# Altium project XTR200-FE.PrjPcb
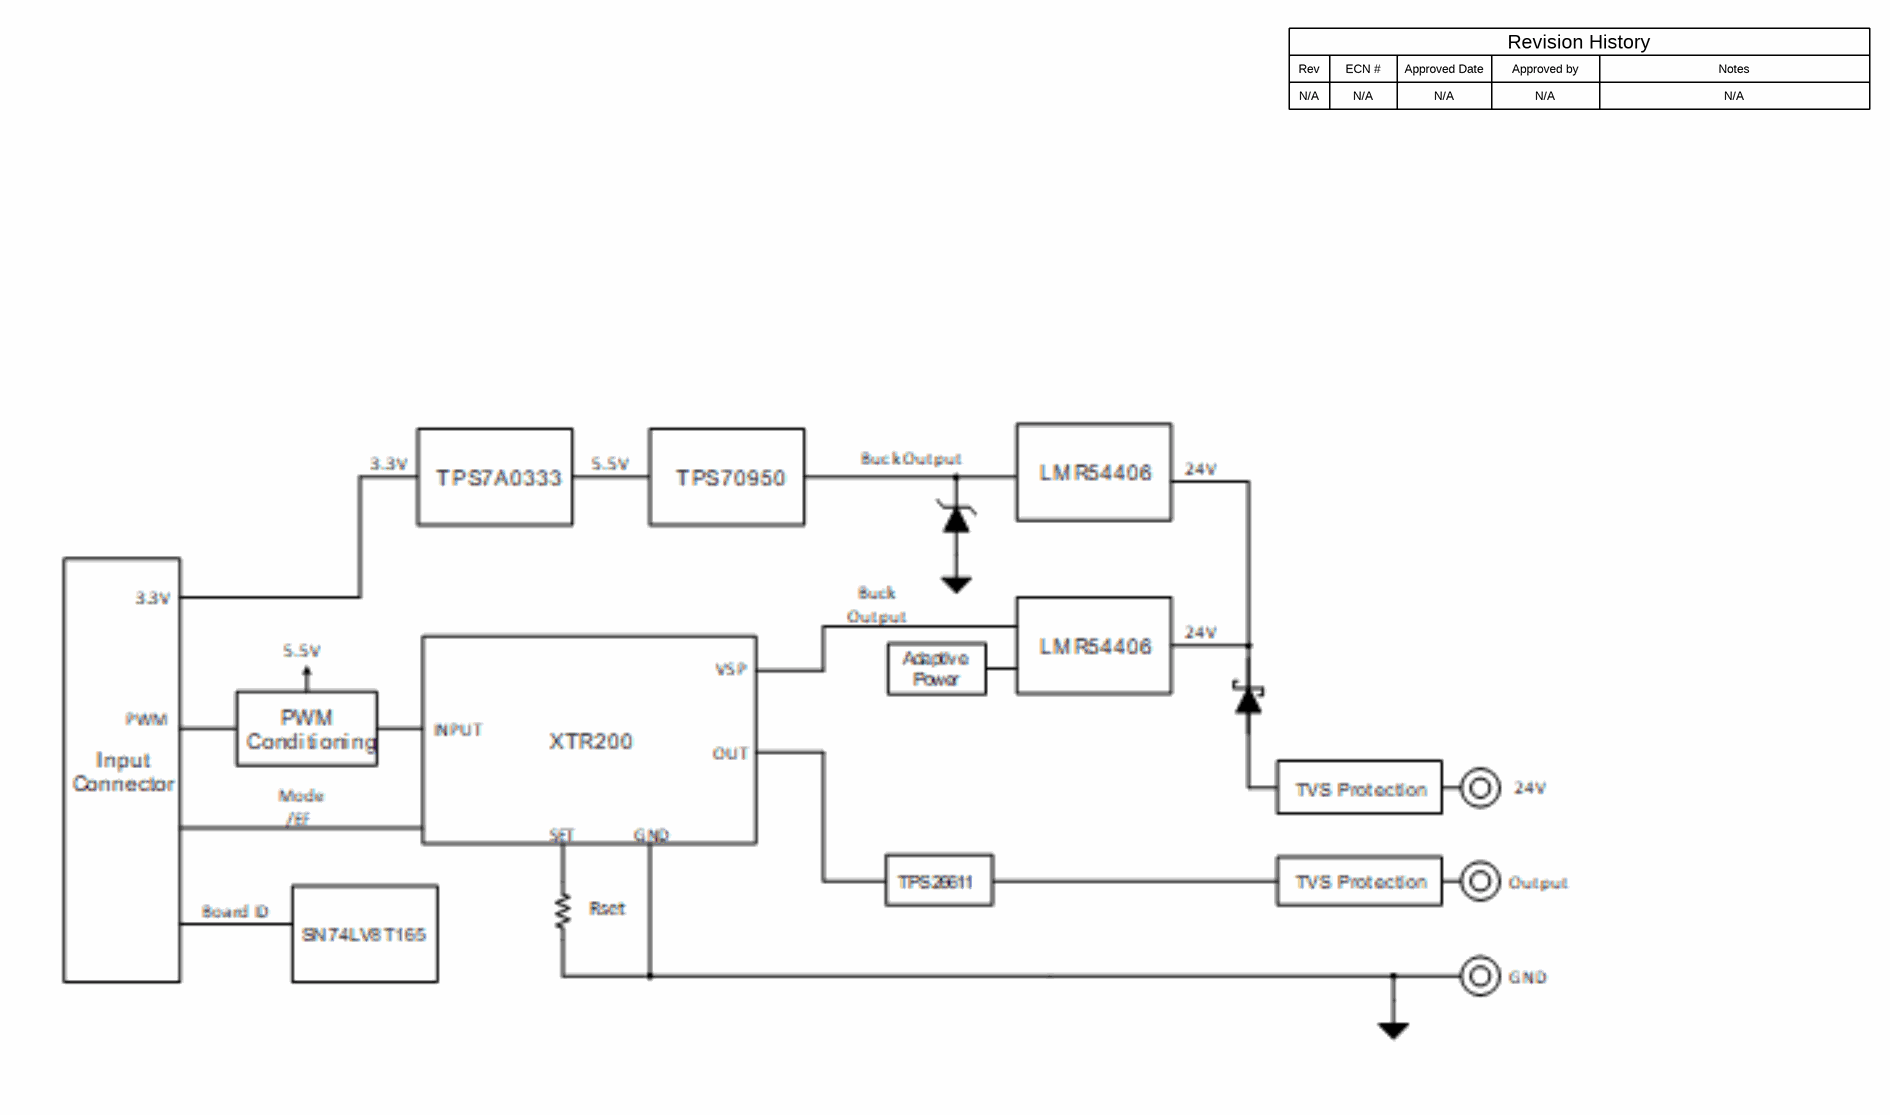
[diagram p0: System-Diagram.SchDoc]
TID: TIDA-011026; TechSupport: http://www.ti.com/support; SCH_Rev: A1; PRJ_Title: FT-EVP-XTR200; PRJ_Number: XTR200_FT; PRJ_Engineer: S. Rojas Avila; PRJ_Customer: Public Release; PCB_Rev: A1; PCB_Layout: S. Rojas Avila; CopyrightYear: 2024
3 sheets, 94 parts. Net scope: global (net labels, ports and power ports of the same name join across sheets).
Board file: XTR200FTA.PcbDoc
Sheets:
  System-Diagram.SchDoc
  Schematic.SchDoc
  Hardware.SchDoc

## Sheet System-Diagram.SchDoc
size 431 x 279 mm; Date: Not shown in title block; ApprovedBy: Not shown in title block; CheckedBy: Not shown in title block; Author: Not shown in title block; CompanyName: Not shown in title block; Engineer: Not shown in title block; Organization: Not shown in title block; Address1: Not shown in title block; Address2: Not shown in title block; Address3: Not shown in title block; Address4: Not shown in title block; DocumentNumber: 1; Revision: Use project parameter SCH_Rev; SheetNumber: 1; SheetTotal: 3; PageSetup: Record=PageOptions¦CenterHorizontal=True¦CenterVertical=True¦PrintScale=1.00¦XCorrection=1.00¦YCorrection=1.00¦PrintKind=0¦BorderSize=5000000¦LeftOffset=0¦BottomOffset=0¦Orientation=2¦PaperLength=1000¦PaperWidth=1000¦Scale=100¦PaperSource=15¦PrintQuality=600¦MediaType=1¦DitherType=10¦PaperKind=Letter¦PrintScaleMode=1

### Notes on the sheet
- Rev
- N/A
- ECN #
- Approved Date
- Approved by
- Revision History
- Notes

## Sheet Schematic.SchDoc
size 431 x 279 mm; Date: Not shown in title block; ApprovedBy: Not shown in title block; CheckedBy: Not shown in title block; Author: Not shown in title block; CompanyName: Not shown in title block; Engineer: Not shown in title block; Organization: Not shown in title block; Address1: Not shown in title block; Address2: Not shown in title block; Address3: Not shown in title block; Address4: Not shown in title block; DocumentNumber: 2; Revision: Use project parameter SCH_Rev; SheetNumber: 2; SheetTotal: 3; PageSetup: Record=PageOptions¦CenterHorizontal=True¦CenterVertical=True¦PrintScale=1.00¦XCorrection=1.00¦YCorrection=1.00¦PrintKind=0¦BorderSize=5000000¦LeftOffset=0¦BottomOffset=0¦Orientation=2¦PaperLength=1000¦PaperWidth=1000¦Scale=100¦PaperSource=15¦PrintQuality=600¦MediaType=1¦DitherType=10¦PaperKind=Letter¦PrintScaleMode=1
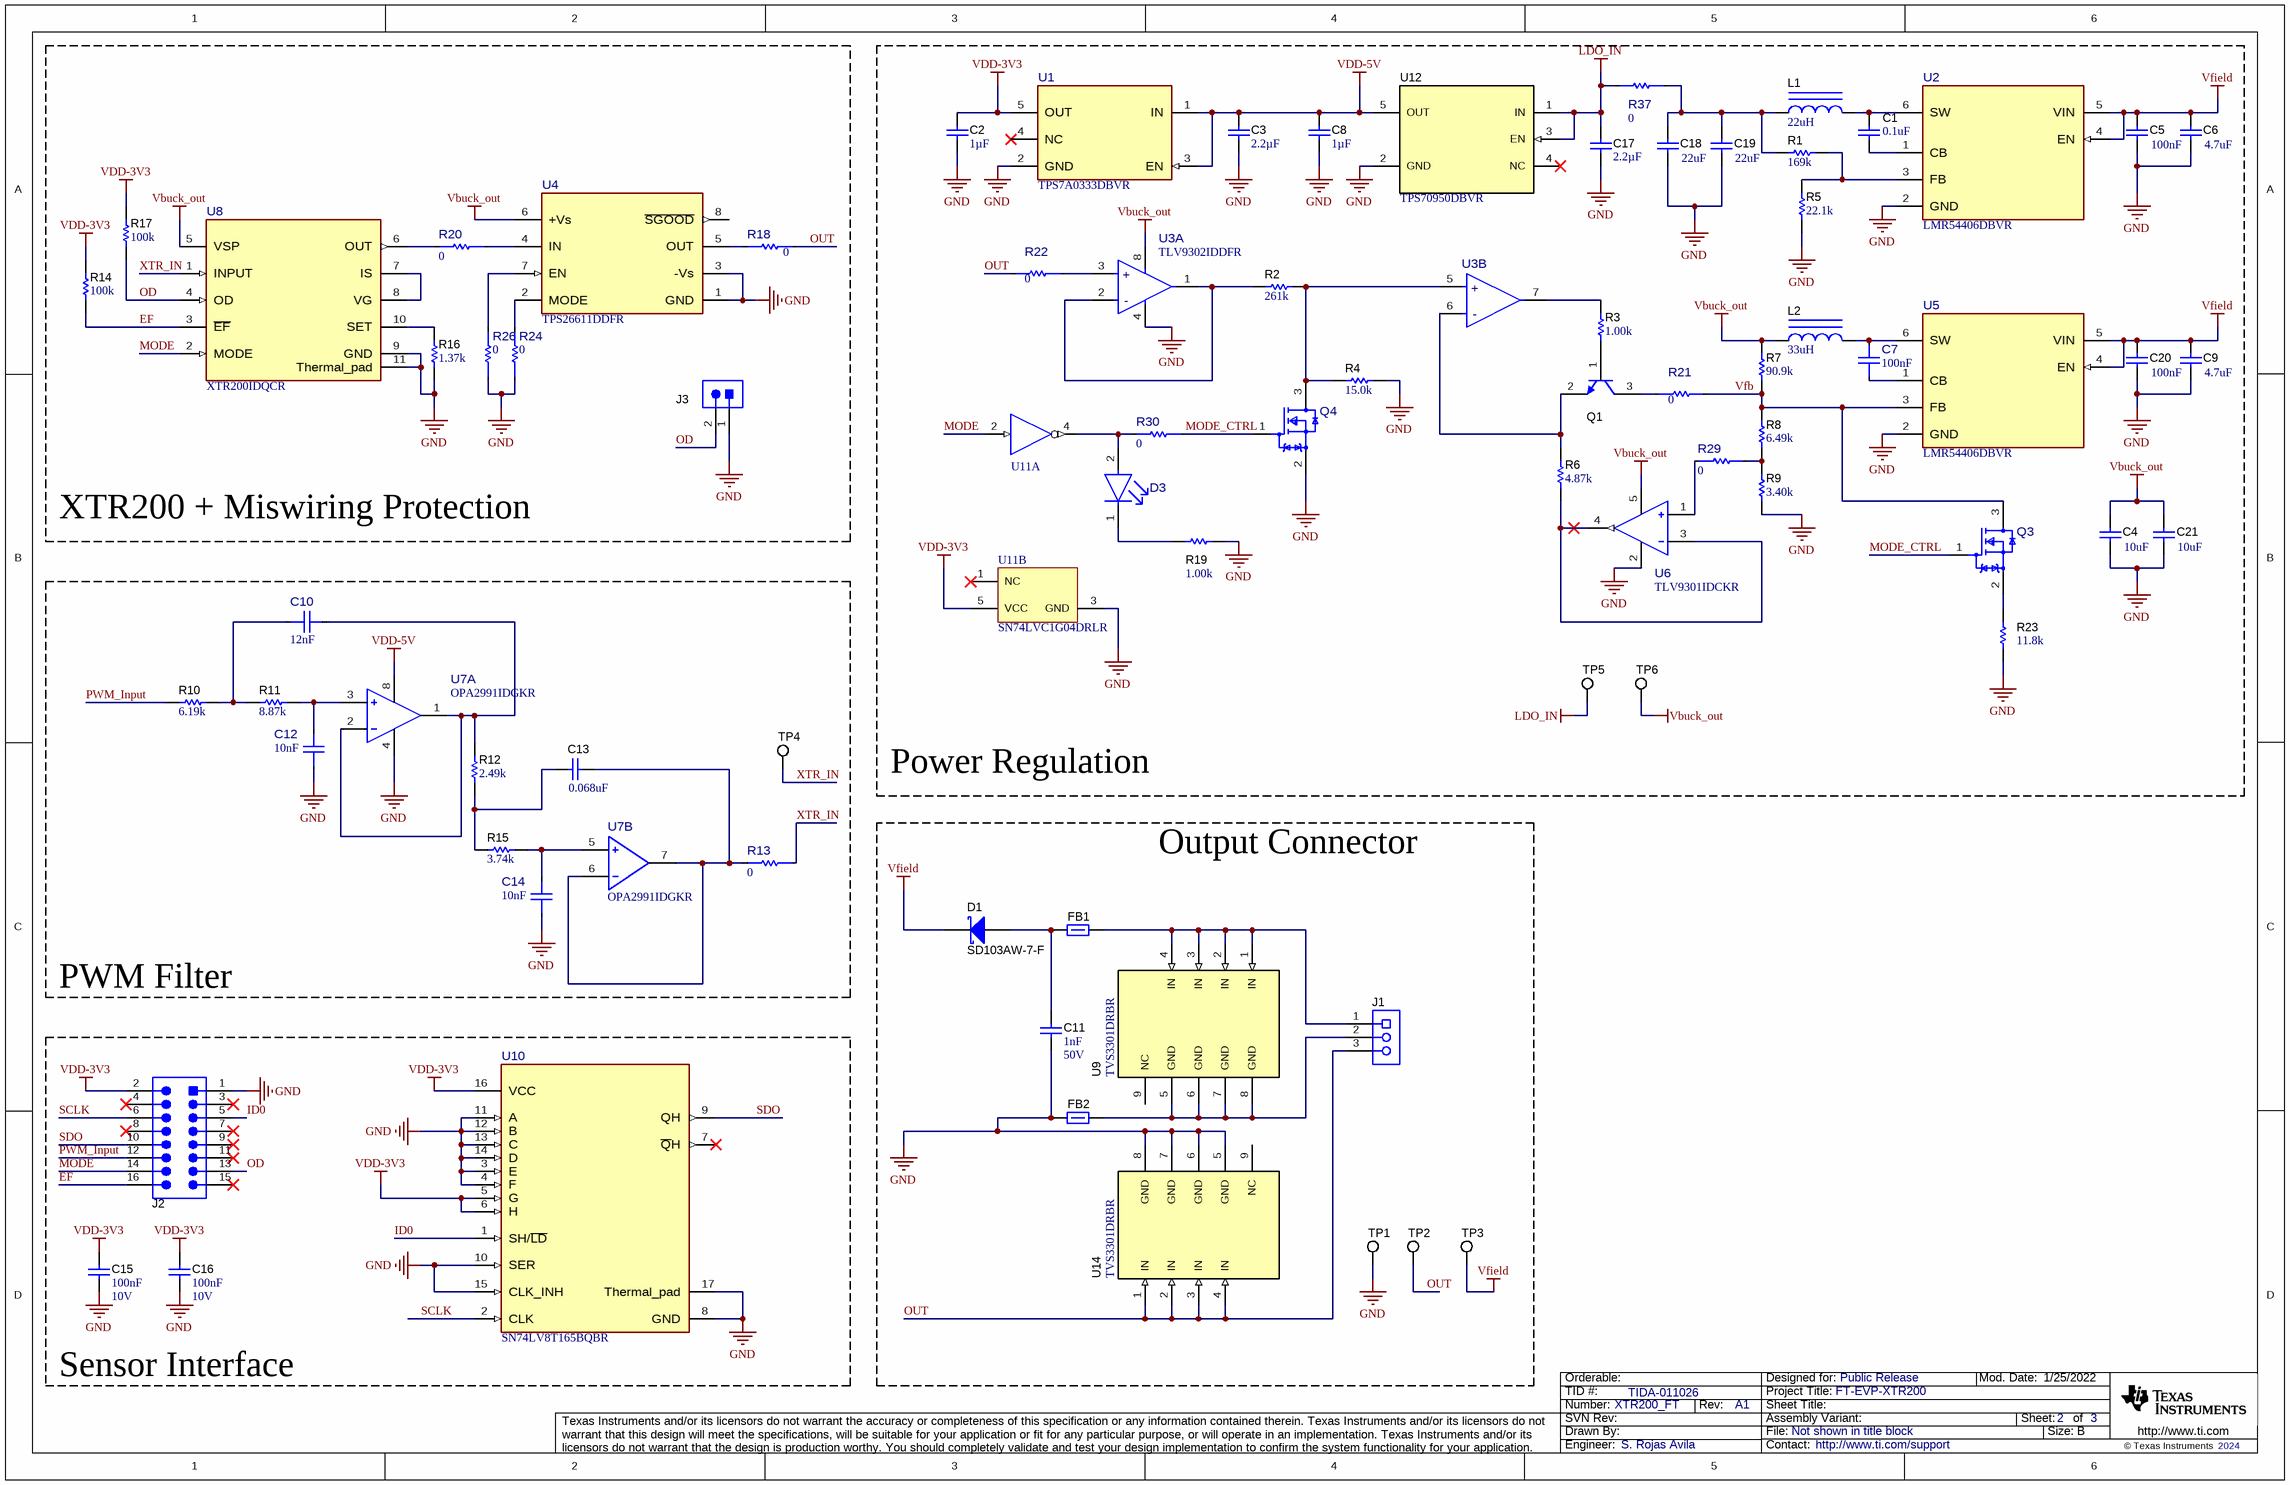
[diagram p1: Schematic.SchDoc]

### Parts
C1  ValueDisplayed: 0.1uF  [0402]  (hidden comment: GRM155R71C104KA88D)
C2  Cap_F: 1µF  [0603]  (hidden comment: 885012206052)
C3  Cap_F: 2.2µF  [0805_HV]  (hidden comment: GRM21BR71C225KA12L)
C4  ValueDisplayed: 10uF  [1206_180]  (hidden comment: C3216X6S1V106K160AC)
C5  Cap_F: 100nF  [0603]  (hidden comment: GRM188R72A104KA35D)
C6  ValueDisplayed: 4.7uF  [1206_180]  (hidden comment: GRM31CR71H475KA12L)
C7  Cap_F: 100nF  [FP-KGF15AR71H104KT_0603-MFG]  (hidden comment: KGF15AR71H104KT)
C8  Cap_F: 1µF  [0603]  (hidden comment: 885012206052)
C9  ValueDisplayed: 4.7uF  [0805_HV]  (hidden comment: GRM21BR61H475KE51L)
C10  ValueDisplayed: 12nF  [FP-CC0402KRX7R7BB123_0402-MFG]  (hidden comment: CC0402KRX7R7BB123)
C11  Cap_F: 1nF  VDC_V: 50V  [0805_HV]  (hidden comment: CC0805KRX7R9BB102)
C12  Cap_F: 10nF  [FP-GRM155R71H103JA88D_0402-MFG]  (hidden comment: GRM155R71H103JA88D)
C13  ValueDisplayed: 0.068uF  [0402]  (hidden comment: GRM155R71C683KA88D)
C14  Cap_F: 10nF  [FP-GRM155R71H103JA88D_0402-MFG]  (hidden comment: GRM155R71H103JA88D)
C15  Cap_F: 100nF  VDC_V: 10V  [0603]  (hidden comment: 885012206020)
C16  Cap_F: 100nF  VDC_V: 10V  [0603]  (hidden comment: 885012206020)
C17  Cap_F: 2.2µF  [0805_HV]  (hidden comment: GRM21BR71C225KA12L)
C18  ValueDisplayed: 22uF  [0805_HV]  (hidden comment: GRM21BR61A226ME44L)
C19  ValueDisplayed: 22uF  [0805_HV]  (hidden comment: GRM21BR61A226ME44L)
C20  Cap_F: 100nF  [0603]  (hidden comment: GRM188R72A104KA35D)
C21  ValueDisplayed: 10uF  [1206_180]  (hidden comment: C3216X6S1V106K160AC)
D1  SD103AW-7-F  [SOD-123]
D3  LTST-C190KFKT  [FP-LTST-C190KFKT_0603-MFG]  (value not drawn)
FB1  742792041  [0805_HV]  (value not drawn)
FB2  742792041  [0805_HV]  (value not drawn)
J1  691412320003  [Wurth_691412320003]  (value not drawn)
J2  61301621021  [Wurth_61301621021]  (value not drawn)
J3  61300211121  [WURTH_61300211121]  (value not drawn)
L1  ValueDisplayed: 22uH  [SRN8040]  (hidden comment: SRN8040-220M)
L2  ValueDisplayed: 33uH  [SRN8040]  (hidden comment: SRN8040-330M)
Q1  MMBT3904LP  [DIODES_X1-DFN1006-3]  (value not drawn)
Q3  NTR4003NT3G  [FP-NTR4003NT3G_SOT23-3-MFG]  (value not drawn)
Q4  NTR4003NT3G  [FP-NTR4003NT3G_SOT23-3-MFG]  (value not drawn)
R1  ValueDisplayed: 169k  [0603]  (hidden comment: CRCW0603169KFKEA)
R2  ValueDisplayed: 261k  [0603]  (hidden comment: CRCW0603261KFKEA)
R3  ValueDisplayed: 1.00k  [0402]  (hidden comment: ERA-2AEB102X)
R4  ValueDisplayed: 15.0k  [0402]  (hidden comment: RC0402FR-0715KL)
R5  ValueDisplayed: 22.1k  [0402]  (hidden comment: CRCW040222K1FKED)
R6  ValueDisplayed: 4.87k  [0603]  (hidden comment: RC0603FR-074K87L)
R7  ValueDisplayed: 90.9k  [0603]  (hidden comment: RC0603FR-0790K9L)
R8  ValueDisplayed: 6.49k  [0603]  (hidden comment: RT0603BRD076K49L)
R9  ValueDisplayed: 3.40k  [0603]  (hidden comment: RT0603BRD073K4L)
R10  ValueDisplayed: 6.19k  [0603]  (hidden comment: RC0603FR-076K19L)
R11  ValueDisplayed: 8.87k  [0603]  (hidden comment: RT0603DRE078K87L)
R12  ValueDisplayed: 2.49k  [0603]  (hidden comment: RT0603DRE072K49L)
R13  value 0  [FP-WSL060300000ZEA9_0603-MFG]  (hidden comment: WSL060300000ZEA9)
R14  ValueDisplayed: 100k  [0603]  (hidden comment: RG1608P-104-B-T5)
R15  ValueDisplayed: 3.74k  [0603]  (hidden comment: RT0603DRE073K74L)
R16  ValueDisplayed: 1.37k  [0603]  (hidden comment: RT0603BRD071K37L)
R17  ValueDisplayed: 100k  [0603]  (hidden comment: RG1608P-104-B-T5)
R18  value 0  [FP-WSL060300000ZEA9_0603-MFG]  (hidden comment: WSL060300000ZEA9)
R19  ValueDisplayed: 1.00k  [0603]  (hidden comment: RT0603DRE071KL)
R20  value 0  [FP-WSL060300000ZEA9_0603-MFG]  (hidden comment: WSL060300000ZEA9)
R21  value 0  [FP-WSL060300000ZEA9_0603-MFG]  (hidden comment: WSL060300000ZEA9)
R22  value 0  [FP-WSL060300000ZEA9_0603-MFG]  (hidden comment: WSL060300000ZEA9)
R23  ValueDisplayed: 11.8k  [0603]  (hidden comment: RT0603BRD0711K8L)
R24  value 0  [FP-WSL060300000ZEA9_0603-MFG]  (hidden comment: WSL060300000ZEA9)
R26  value 0  [FP-WSL060300000ZEA9_0603-MFG]  (hidden comment: WSL060300000ZEA9)
R29  value 0  [FP-WSL060300000ZEA9_0603-MFG]  (hidden comment: WSL060300000ZEA9)
R30  value 0  [FP-WSL060300000ZEA9_0603-MFG]  (hidden comment: WSL060300000ZEA9)
R37  value 0  [FP-WSL060300000ZEA9_0603-MFG]  (hidden comment: WSL060300000ZEA9)
TP1  GND  [Keystone5002]  (value not drawn)
TP2  GND  [Keystone5002]  (value not drawn)
TP3  GND  [Keystone5002]  (value not drawn)
TP4  GND  [Keystone5002]  (value not drawn)
TP5  GND  [Keystone5002]  (value not drawn)
TP6  GND  [Keystone5002]  (value not drawn)
U1  TPS7A0333DBVR  [DBV0005A-MFG]
U2  LMR54406DBVR  [DBV0006A-MFG]
U3  TLV9302IDDFR  [DDF0008A-MFG]  (parts A,B of 2)
U4  TPS26611DDFR  [DDF0008A-MFG]
U5  LMR54406DBVR  [DBV0006A-MFG]
U6  TLV9301IDCKR  [DCK0005A-MFG]
U7  OPA2991IDGKR  [DGK0008A-MFG]  (parts A,B of 2)
U8  XTR200IDQCR  [DQC0010A-MFG]
U9  TVS3301DRBR  [DRB0008A]
U10  SN74LV8T165BQBR  [BQB0016A-MFG]
U11  SN74LVC1G04DRLR  [DRL0005A]  (value not drawn)  (parts A,B of 2)
U12  TPS70950DBVR  [DBV0005A_N]
U14  TVS3301DRBR  [DRB0008A]

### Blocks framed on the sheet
XTR200 + Miswiring Protection: J3 R14 R16-R18 R20 R24 R26 U4 U8
Power Regulation: C1-C9 C17-C21 D3 L1 L2 Q1 Q3 Q4 R1-R9 R19 R21-R23 R29 R30 R37 TP5 TP6 U1-U3 U5 U6 U11 U12
PWM Filter: C10 C12-C14 R10-R13 R15 TP4 U7
Output Connector: C11 D1 FB1 FB2 J1 TP1-TP3 U9 U14
Sensor Interface: C15 C16 J2 U10

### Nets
GND: C2.1 C3.1 C4.1 C5.2 C6.2 C8.1 C9.2 C11.2 C12.1 C14.1 C15.2 C16.2 C17.1 C18.2 C19.2 C20.2 C21.1 FB2.1 J2.1 J3.1 Q4.2(SOURCE) R4.1 R5.1 R9.1 R16.1 R19.2 R23.1 R24.1 R26.1 TP1.1 U1.2(GND) U2.2(GND) U3.4(V-) U4.1(GND) U4.3(-Vs) U5.2(GND) U6.2(V-) U7.4(V-) U8.9(GND) U8.11(Thermal_pad) U10.3(E) U10.4(F) U10.8(GND) U10.10(SER) U10.11(A) U10.12(B) U10.13(C) U10.14(D) U10.15(CLK_INH) U10.17(Thermal_pad) U11.3(GND) U12.2(GND) U14.5(GND) U14.6(GND) U14.7(GND) U14.8(GND)
LDO_IN: C17.2 R37.2 TP5.1 U12.1(IN) U12.3(EN)
Vbuck_out: C4.2 C21.2 L2.1 R7.2 TP6.1 U3.8(V+) U4.6(+Vs) U6.5(V+) U8.5(VSP)
VDD-3V3: C2.2 C15.1 C16.1 J2.2 R14.2 R17.2 U1.5(OUT) U10.5(G) U10.6(H) U10.16(VCC) U11.5(VCC)
VDD-5V: C3.2 C8.2 U1.1(IN) U1.3(EN) U7.8(v+) U12.5(OUT)
Vfield: C5.1 C6.1 C9.1 C20.1 D1.1(K) TP3.1 U2.4(EN) U2.5(VIN) U5.4(EN) U5.5(VIN)
EF: J2.16 R14.1 U8.3(~{EF})
ID0: J2.5 U10.1(SH/~{LD})
MODE: J2.14 U8.2(MODE) U11.2(A)
MODE_CTRL: Q3.1(GATE) Q4.1(GATE) R30.1
OD: J2.13 J3.2 R17.1 U8.4(OD)
OUT: J1.3 R18.1 R22.2 TP2.1 U14.1(IN) U14.2(IN) U14.3(IN) U14.4(IN)
PWM_Input: J2.12 R10.1
SCLK: J2.6 U10.2(CLK)
SDO: J2.10 U10.9(QH)
Vfb: Q3.3(DRAIN) R7.1 R8.2 R21.2 U5.3(FB)
XTR_IN: R13.1 TP4.1 U8.1(INPUT)
NetC1_1: C1.1 L1.2 U2.6(SW)
NetC1_2: C1.2 U2.1(CB)
NetC7_1: C7.1 U5.1(CB)
NetC7_2: C7.2 L2.2 U5.6(SW)
NetC10_1: C10.1 R10.2 R11.1
NetC10_2: C10.2 R12.2 U7.1(OUT1) U7.2(IN1-)
NetC11_1: C11.1 D1.2(A) FB1.1
NetC12_2: C12.2 R11.2 U7.3(IN1+)
NetC13_1: C13.1 R13.2 U7.6(IN2-) U7.7(OUT2)
NetC13_2: C13.2 R12.1 R15.1
NetC14_2: C14.2 R15.2 U7.5(IN2+)
NetC18_1: C18.1 C19.1 L1.1 R1.2 R37.1
NetD3_1: D3.1(CATHODE) R19.1
NetD3_2: D3.2(ANODE) R30.2 U11.4(Y)
NetFB1_2: FB1.2 J1.1 U9.1(IN) U9.2(IN) U9.3(IN) U9.4(IN)
NetFB2_2: FB2.2 J1.2 U9.5(GND) U9.6(GND) U9.7(GND) U9.8(GND)
NetQ1_1: Q1.1(B) R3.2
NetQ1_2: Q1.2(E) R6.2 U3.6(IN2-)
NetQ1_3: Q1.3(C) R21.1
NetQ3_2: Q3.2(SOURCE) R23.2
NetQ4_3: Q4.3(DRAIN) R2.2 R4.2 U3.5(IN2+)
NetR1_1: R1.1 R5.2 U2.3(FB)
NetR2_1: R2.1 U3.1(OUT1) U3.2(IN1-)
NetR3_1: R3.1 U3.7(OUT2)
NetR6_1: R6.1 U6.3(IN-) U6.4(OUT)
NetR8_1: R8.1 R9.2 R29.2
NetR16_2: R16.2 U8.10(SET)
NetR18_2: R18.2 U4.5(OUT)
NetR20_1: R20.1 U4.4(IN)
NetR20_2: R20.2 U8.6(OUT)
NetR22_1: R22.1 U3.3(IN1+)
NetR24_2: R24.2 U4.2(MODE)
NetR26_2: R26.2 U4.7(EN)
NetR29_1: R29.1 U6.1(IN+)
NetU8_7: U8.7(IS) U8.8(VG)

Not connected (* = marked no-connect by the designer): J2 3* 4* 7* 8* 9* 11* 15*; U1 4(NC)*; U4 8(~{SGOOD}); U9 9(NC); U10 7(~{Q}H)*; U11 1(NC)*; U12 4(NC)*; U14 9(NC)

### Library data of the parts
C1 = CMP-0006641-2: CAP, CERM, 0.1 uF, 16 V, +/- 10%, X7R, 0402; Manufacturer: MuRata; TaMin_C: -55°C; Polarized: N; SizeAreaWB_mm2: 3; Value1: Unknown; U/M: EA; Value: 0.1uF; TaMax_C: 125°C; SizeZ_mm: 0.6; SizeX_mm: 1; SizeY_mm: 0.5; Value2: 16V; Cap_F: 100nF; AEC Category: Q200
C2 C8 = CMP-0006831-4: CAP, CERM, 1 uF, 16 V, +/- 10%, X7R, 0603; Manufacturer: Wurth Elektronik; TaMin_C: -55°C; Polarized: N; SizeAreaWB_mm2: 4.68; Value1: Unknown; U/M: EA; Value: 1uF; TaMax_C: 125°C; SizeZ_mm: 1; SizeX_mm: 1.6; SizeY_mm: 0.8; Value2: 16V; SizeArea_mm2: 1.28; AEC Category: Q200
C3 C17 = CMP-0008329-2: CAP, CERM, 2.2 uF, 16 V, +/- 10%, X7R, 0805; Manufacturer: MuRata; TaMin_C: -55°C; ESR_ohm: 4m; Polarized: N; SizeAreaWB_mm2: 6.75; Value1: 0.004 ohm; U/M: EA; Value: 2.2uF; TaMax_C: 125°C; SizeZ_mm: 1.45; SizeX_mm: 2; SizeY_mm: 1.25; Cap_Case: 0805; Value2: 16V; SizeArea_mm2: 2.5; AEC Category: Q200
C4 C21 = CMP-0008684-3: CAP, CERM, 10 uF, 35 V, +/- 10%, X6S, 1206; Manufacturer: TDK; TaMin_C: -55°C; ESR_ohm: 2.229m; Polarized: N; SizeAreaWB_mm2: 10.92; Value1: 0.002229 ohm; U/M: EA; Value: 10uF; TaMax_C: 105°C; SizeZ_mm: 1.8; SizeX_mm: 3.2; SizeY_mm: 1.6; Value2: 35V; SizeArea_mm2: 5.12; Cap_F: 10µF; IRMS_A: 4.85932A; AEC Category: Q200
C5 C20 = CMP-0007469-4: CAP, CERM, 0.1 uF, 100 V, +/- 10%, X7R, 0603; Manufacturer: MuRata; TaMin_C: -55°C; Polarized: N; SizeAreaWB_mm2: 4.68; Value1: Unknown; U/M: EA; Value: 0.1uF; TaMax_C: 125°C; SizeZ_mm: 1; SizeX_mm: 1.6; SizeY_mm: 0.8; Value2: 100V; SizeArea_mm2: 1.28; AEC Category: Q200
C6 = CMP-0008969-2: CAP, CERM, 4.7 uF, 50 V, +/- 10%, X7R, 1206; Manufacturer: MuRata; TaMin_C: -55°C; Polarized: N; SizeAreaWB_mm2: 10.92; Value1: Unknown; U/M: EA; Value: 4.7uF; TaMax_C: 125°C; SizeZ_mm: 1.8; SizeX_mm: 3.2; SizeY_mm: 1.6; Cap_Case: 2220; Value2: 50V; SizeArea_mm2: 5.12; Cap_F: 4.7µF; AEC Category: Q200
C7 = CMP-0121004-1: 0.1 µF ±10% 50V Ceramic Capacitor X7R 0603 (1608 Metric); Manufacturer: KYOCERA AVX; AEC Qualified: No; SizeZ_mm: 0.9mm; TempCo: 15%; Value: 100nF
C9 = CMP-0008309-2: CAP, CERM, 4.7 uF, 50 V, +/- 10%, X5R, 0805; Manufacturer: MuRata; TaMin_C: -55°C; Polarized: N; SizeAreaWB_mm2: 6.75; Value1: Unknown; U/M: EA; Value: 4.7uF; TaMax_C: 85°C; SizeZ_mm: 1.45; SizeX_mm: 2; SizeY_mm: 1.25; Cap_Case: 0805; Value2: 50V; SizeArea_mm2: 2.5; Cap_F: 4.7µF; AEC Category: Q200
C10 = CMP-0109222-1: 0.012 µF ±10% 16V Ceramic Capacitor X7R 0402 (1005 Metric); Manufacturer: Yageo; AEC Qualified: No; SizeZ_mm: 0.55mm; TempCo: 15%; Value: 12nF
C11 = CMP-0007936-2: CAP, CERM, 1000 pF, 50 V, +/- 10%, X7R, 0805; Manufacturer: Yageo America; TaMin_C: -55°C; Polarized: N; SizeAreaWB_mm2: 6.75; Value1: Unknown; U/M: EA; Value: 1000pF; TaMax_C: 125°C; SizeZ_mm: 1.45; SizeX_mm: 2; SizeY_mm: 1.25; Cap_Case: 0805; SizeArea_mm2: 2.5; AEC Category: Q200
C12 C14 = CMP-0096544-1: Chip Multilayer Ceramic Capacitors for General Purpose, 0402, 10000pF, X7R, 15%, 5%, 50V; Manufacturer: Murata; Value: 10nF; SizeZ_mm: 0.55mm; AEC Qualified: No
C13 = CMP-0006655-2: CAP, CERM, 0.068 uF, 16 V, +/- 10%, X7R, 0402; Manufacturer: MuRata; TaMin_C: -55°C; Polarized: N; SizeAreaWB_mm2: 3; Value1: Unknown; U/M: EA; TaMax_C: 125°C; SizeZ_mm: 0.6; SizeX_mm: 1; SizeY_mm: 0.5; Value2: 16V; Cap_F: 68nF; AEC Category: Q200
C15 C16 = CMP-0064931-4: CAP, CERM, 0.1 uF, 10 V,+/- 10%, X7R, 0603; Manufacturer: Wurth Elektronik; TaMin_C: -55°C; Polarized: N; SizeAreaWB_mm2: 4.68; Value1: Unknown; U/M: EA; Value: 0.1uF; TaMax_C: 125°C; SizeZ_mm: 1; SizeX_mm: 1.6; SizeY_mm: 0.8; SizeArea_mm2: 1.28; AEC Category: Q200
C18 C19 = CMP-0008286-2: CAP, CERM, 22 uF, 10 V, +/- 20%, X5R, 0805; Manufacturer: MuRata; TaMin_C: -55°C; Polarized: N; SizeAreaWB_mm2: 6.75; Value1: Unknown; U/M: EA; Value: 22uF; TaMax_C: 85°C; SizeZ_mm: 1.45; SizeX_mm: 2; SizeY_mm: 1.25; Cap_Case: 0805; Value2: 10V; SizeArea_mm2: 2.5; Cap_F: 22µF; AEC Category: Q200
D1 = CMP-0028543-2: Diode, Schottky, 40 V, 0.35 A, SOD-123; Manufacturer: Diodes Inc.; AEC Category: Q101; Io_A: 350mA; SizeZ_mm: 1.35; Vf_V: 550mV; Green_REACh: Passed; SizeAreaWB_mm2: 13.095; SizeY_mm: 1.7; SizeX_mm: 3.85; Value2: 0.55V; Green_Lifecycle: Active; Vr_V: 40V; Value1: 0.35A; SizeArea_mm2: 6.545; Value: 40V
D3 = CMP-0097262-1: Orange 605nm LED Indication - Discrete 2V 0603 (1608 Metric); Manufacturer: Lite-On; Vr_V: 5V; SizeZ_mm: 0.9mm; AEC Qualified: No; Led Orientation: Top View; Forward Current: 20mA; Power_TotalModule: 75mW; Luminous Intensity: 90mcd; LambdaP: 611nm; Angle: 130°
FB1 FB2 = CMP-0003085-1: Ferrite Bead, 600 ohm @ 100 MHz, 0.2 A, 0805; Manufacturer: Wurth Elektronik; Ztyp@1GHz_Ohm: 200.287; ZTyp@100MHz_Ohm: 600; SizeAreaWB_mm2: 6.75; DCR_ohm: 0.4; Value1: 0.4 ohm; Value: 600 ohm; Imax_A: 200mA; SizeZ_mm: 1.45; SizeX_mm: 2; SizeY_mm: 1.25; Value2: 0.2A; SizeArea_mm2: 2.5
J1 = CMP-0083843-1: Terminal Block, 3 Position, 3.81mm, Tin, R/A, TH; Manufacturer: Wurth Elektronik; Pitch_mm: 3.81; Voltage_V: 300V; Cert_UL: Y; Gender: Female; Current_A: 4A; Row_Count: 1
J2 = CMP-0081505-1: Header, 2.54mm, 8x2, Gold, R/A, TH; Manufacturer: Wurth Elektronik; Pitch_mm: 2.54; Gender: Male; Cert_UL: Y; Current_A: 3A; Voltage_V: 250V; Shrouded: N; Row_Count: 2
J3 = CMP-0054794-2: Header, 2.54 mm, 2x1, Gold, TH; Manufacturer: Wurth Elektronik; Shrouded: N; Gender: Male; Green_REACh: Passed; Pitch_mm: 2.54; Green_Lifecycle: Active; Row_Count: 1; Cert_UL: Y
L1 = CMP-0057669-2: Inductor, Drum Core, Ferrite, 22 uH, 2.2 A, 0.1 ohm, SMD; Manufacturer: Bourns; Isat: 2.2A @ 30% inductance drop; Irms: 2.2A @ 40C rise; Green_Lifecycle: Active; SizeAreaWB_mm2: 100; DCR_ohm: 1d; Green_REACh: Passed; Value1: 0.1 ohm; Value: 22uH; Imax_A: 2.2A; SizeZ_mm: 4; SizeX_mm: 8; SizeArea_mm2: 64; Ind_H: 22µH; AEC Category: Q200
L2 = CMP-0057670-2: Inductor, Drum Core, Ferrite, 33 uH, 1.7 A, 0.145 ohm, SMD; Manufacturer: Bourns; Isat: 1.9A @ 30% inductance drop; Irms: 1.7A @ 40C rise; Green_Lifecycle: Active; SizeAreaWB_mm2: 100; DCR_ohm: 1.45d; Green_REACh: Passed; Value: 33uH; Imax_A: 1.7A; SizeZ_mm: 4; SizeX_mm: 8; SizeArea_mm2: 64; Ind_H: 33µH; AEC Category: Q200
Q1 = CMP-0000409-2: Transistor, NPN, 40 V, 0.2 A, 3-UFDFN; Manufacturer: Diodes Inc.; TaMax_C: 150°C; Value2: 400; Value1: 0.2 A; Vcesat1_V: 3dV; SizeX_mm: 1; SizeY_mm: 0.6; TaMin_C: -55°C; IcRated_A: 2dA; CompType: BJT; SizeZ_mm: 0.53; Value: 40 V; Vceo_V: 40V; PNP: 0; AEC Category: Q101; SizeAreaWB_mm2: 3.2; U/M: EA
Q3 Q4 = CMP-0125365-1: N-Channel 30V 500mA (Ta) 690mW (Ta) Surface Mount SOT-23-3 (TO-236); Manufacturer: On Semiconductor; AEC Qualified: No; QgTyp_nC: 1.15nC @ 5V; Rdson45_ohm: 1; SizeZ_mm: 1.11mm; VdsMax_V: 700mV; Vgs_V: 20V; ChMode: False; Ciiva Ids: 19302475; Import Ts: 1521847768; Input Capacitace At Vds: 21pF @ 5V; Power_W: 0.69W; Pulse Drain Current: 1.7A; Reverse Recovery Time: 14ns; Rthja Max: 300°C/W; Standoff Height: 0.01mm; Threshold Vgs Max: 1.4V; Threshold Vgs Min: 0.8V; TJmax_C: +150°C; Transconductance: 0.33S; Turn Off Delay Time: 65.1ns; Turn On Delay Time: 16.7ns; Typ Forward Diode Voltage: 0.65V
R1 = CMP-0022077-4: RES, 169 k, 1%, 0.1 W, AEC-Q200 Grade 0, 0603; Manufacturer: Vishay-Dale; Power_W: 100mW; TempCo: 100 ppm/C; Value: 169k; EIA_Code: E96; SizeX_mm: 1.6; SizeY_mm: 0.8; SizeZ_mm: 1; Value2: 0.1W; SizeArea_mm2: 1.28; AEC Qualified: Y; VDC_V: 75V; AEC Category: Q200; AEC Grade: 0
R2 = CMP-0022244-4: RES, 261 k, 1%, 0.1 W, AEC-Q200 Grade 0, 0603; Manufacturer: Vishay-Dale; Power_W: 100mW; TempCo: 100 ppm/C; Value: 261k; EIA_Code: E96; SizeX_mm: 1.6; SizeY_mm: 0.8; SizeZ_mm: 1; Value2: 0.1W; SizeArea_mm2: 1.28; AEC Qualified: Y; VDC_V: 75V; AEC Category: Q200; AEC Grade: 0
R3 = CMP-0026770-1: RES, 1.00 k, 0.1%, 0.063 W, 0402; Manufacturer: Panasonic; Power_W: 63mW; TempCo: 25 ppm/C; Value_Code: 1k00; U/M: EA; Value: 1.00k; EIA_Code: E192; Res_ohm: 1k; SizeX_mm: 1; SizeY_mm: 0.5; SizeZ_mm: 0.6; Value2: 0.063W; VDC_V: 50V; AEC Category: Q200
R4 = CMP-0078583-1: RES, 15.0 k, 1%, 0.063 W, 0402; Manufacturer: Yageo America; Power_W: 63mW; Green_Lifecycle: Active; TempCo: 100 ppm/C; Value_Code: 15k0; Green_REACh: Passed; Value: 15.0k; EIA_Code: E96; Res_ohm: 15k; SizeX_mm: 1; SizeY_mm: 0.5; SizeZ_mm: 0.6; Value2: 0.063W; AEC Qualified: N; AEC Category: Q200
R5 = CMP-0026178-2: RES, 22.1 k, 1%, 0.063 W, AEC-Q200 Grade 0, 0402; Manufacturer: Vishay-Dale; Power_W: 63mW; TempCo: 100 ppm/C; Value_Code: 22k1; Value: 22.1k; EIA_Code: E96; SizeX_mm: 1; SizeY_mm: 0.5; SizeZ_mm: 0.6; Value2: 0.063W; AEC Qualified: Y; VDC_V: 50V; AEC Category: Q200; AEC Grade: 0
R6 = CMP-0023154-5: RES, 4.87 k, 1%, 0.1 W, 0603; Manufacturer: Yageo; Power_W: 100mW; TempCo: 100 ppm/C; Value_Code: 4k87; Value: 4.87k; EIA_Code: E96; SizeX_mm: 1.6; SizeY_mm: 0.8; SizeZ_mm: 1; Value2: 0.1W; SizeArea_mm2: 1.28; AEC Qualified: N; VDC_V: 75V; AEC Category: Q200; SizeAreaWB_mm2: 4.68
R7 = CMP-0023314-5: RES, 90.9 k, 1%, 0.1 W, 0603; Manufacturer: Yageo; Power_W: 100mW; TempCo: 100 ppm/C; Value_Code: 90k9; Value: 90.9k; EIA_Code: E96; SizeX_mm: 1.6; SizeY_mm: 0.8; SizeZ_mm: 1; Value2: 0.1W; SizeArea_mm2: 1.28; AEC Qualified: N; VDC_V: 75V; AEC Category: Q200; SizeAreaWB_mm2: 4.68
R8 = CMP-0024436-2: RES, 6.49 k, 0.1%, 0.1 W, 0603; Manufacturer: Yageo America; Power_W: 100mW; TempCo: 25 ppm/C; Value_Code: 6k49; U/M: EA; Value: 6.49k; EIA_Code: E192; SizeX_mm: 1.6; SizeY_mm: 0.8; SizeZ_mm: 1; Value2: 0.1W; SizeArea_mm2: 1.28; VDC_V: 75V; AEC Category: Q200
R9 = CMP-0024198-2: RES, 3.40 k, 0.1%, 0.1 W, 0603; Manufacturer: Yageo America; Power_W: 100mW; TempCo: 25 ppm/C; Value_Code: 3k40; U/M: EA; Value: 3.40k; EIA_Code: E192; Res_ohm: 3.4k; SizeX_mm: 1.6; SizeY_mm: 0.8; SizeZ_mm: 1; Value2: 0.1W; SizeArea_mm2: 1.28; VDC_V: 75V; AEC Category: Q200
R10 = CMP-0023247-5: RES, 6.19 k, 1%, 0.1 W, 0603; Manufacturer: Yageo; Power_W: 100mW; TempCo: 100 ppm/C; Value_Code: 6k19; Value: 6.19k; EIA_Code: E96; SizeAreaWB_mm2: 4.68; SizeX_mm: 1.6; SizeY_mm: 0.8; SizeZ_mm: 1; Value2: 0.1W; SizeArea_mm2: 1.28; AEC Qualified: N; VDC_V: 75V; AEC Category: Q200
R11 = CMP-0025632-3: RES, 8.87 k, 0.5%, 0.1 W, 0603; Manufacturer: Yageo America; Power_W: 100mW; TempCo: 50 ppm/C; Value_Code: 8k87; U/M: EA; Value: 8.87k; EIA_Code: E192; SizeX_mm: 1.6; SizeY_mm: 0.8; SizeZ_mm: 1; Value2: 0.1W; SizeArea_mm2: 1.28; VDC_V: 75V; AEC Category: Q200
R12 = CMP-0025063-3: RES, 2.49 k, 0.5%, 0.1 W, 0603; Manufacturer: Yageo America; Power_W: 100mW; TempCo: 50 ppm/C; Value_Code: 2k49; U/M: EA; Value: 2.49k; EIA_Code: E192; SizeX_mm: 1.6; SizeY_mm: 0.8; SizeZ_mm: 1; Value2: 0.1W; SizeArea_mm2: 1.28; VDC_V: 75V; AEC Category: Q200
R13 R18 R20-R22 R24 R26 R29 R30 R37 = CMP-0031931-1: 0 Ohms Jumper Chip Resistor 0603 (1608 Metric) Metal Element; Manufacturer: Vishay; AEC Qualified: No; SizeZ_mm: 0.457mm; TempCo: 3900ppm/°C
R14 R17 = CMP-0023405-3: RES, 100 k, 0.1%, 0.1 W, 0603; Manufacturer: Susumu Co Ltd; Power_W: 100mW; TempCo: 25 ppm/C; U/M: EA; Value: 100k; EIA_Code: E192; SizeX_mm: 1.6; SizeY_mm: 0.8; SizeZ_mm: 1; Value2: 0.1W; SizeArea_mm2: 1.28; VDC_V: 75V; AEC Category: Q200
R15 = CMP-0025228-3: RES, 3.74 k, 0.5%, 0.1 W, 0603; Manufacturer: Yageo America; Power_W: 100mW; TempCo: 50 ppm/C; Value_Code: 3k74; U/M: EA; Value: 3.74k; EIA_Code: E192; SizeX_mm: 1.6; SizeY_mm: 0.8; SizeZ_mm: 1; Value2: 0.1W; SizeArea_mm2: 1.28; VDC_V: 75V; AEC Category: Q200
R16 = CMP-0023886-3: RES, 1.37 k, 0.1%, 0.1 W, 0603; Manufacturer: Yageo America; Power_W: 100mW; TempCo: 25 ppm/C; Value_Code: 1k37; U/M: EA; Value: 1.37k; EIA_Code: E192; SizeX_mm: 1.6; SizeY_mm: 0.8; SizeZ_mm: 1; Value2: 0.1W; SizeArea_mm2: 1.28; VDC_V: 75V; AEC Category: Q200
R19 = CMP-0024852-2: RES, 1.00 k, 0.5%, 0.1 W, 0603; Manufacturer: Yageo America; Power_W: 100mW; TempCo: 50 ppm/C; Value_Code: 1k00; U/M: EA; Value: 1.00k; EIA_Code: E192; Res_ohm: 1k; SizeX_mm: 1.6; SizeY_mm: 0.8; SizeZ_mm: 1; Value2: 0.1W; SizeArea_mm2: 1.28; VDC_V: 75V; AEC Category: Q200
R23 = CMP-0023681-3: RES, 11.8 k, 0.1%, 0.1 W, 0603; Manufacturer: Yageo America; Power_W: 100mW; TempCo: 25 ppm/C; Value_Code: 11k8; U/M: EA; Value: 11.8k; EIA_Code: E192; SizeX_mm: 1.6; SizeY_mm: 0.8; SizeZ_mm: 1; Value2: 0.1W; SizeArea_mm2: 1.28; VDC_V: 75V; AEC Category: Q200
TP1-TP6 = CMP-0055139-2: Test Point, Miniature, White, TH; Manufacturer: Keystone Electronics; ContactFinish: Silver; Green_REACh: Passed; CT: TRUE; Green_Lifecycle: Active; CNHeader: FALSE
U1 = CMP-0123072-1: Nanopower-IQ 200nA 200mA low-dropout (LDO) voltage regulator with fast transient response; Manufacturer: Texas Instruments; SizeZ_mm: 1.45mm; AEC Qualified: No; Accuracy Percentage: 1%; Dropout Voltage: 310mV; Max Supply Voltage: 6V; Min Supply Voltage: 3.8V; Nominal Supply Current: 0.2uA; Number Of Outputs: 1; Output Type: Fixed; Output Voltage: 3.3V; Standoff Height: 0mm; TJmax_C: +125°C
U2 U5 = CMP-0093103-2: Buck Converter, Adjustable, 4V-36V Input, 1-28V 1A Output, SOT23-6; Manufacturer: Texas Instruments; Output Type: AdjustableProgrammable; Max Supply Voltage: 36V; TJmax_C: +150°C; Min Supply Voltage: 4V; CompType: IC; Switching Frequency: 700kHz; AEC Qualified: No; Standoff Height: 0mm; Nominal Supply Current: 80uA; AEC Category: Q200; Max Duty Cycle: 98%; Number Of Outputs: 1; SizeZ_mm: 1.45mm
U3 = CMP-0127304-1: Dual, 40-V, 1-MHz, low-power operational amplifier 8-SOT-23-THIN -40 to 125; Manufacturer: Texas Instruments; SizeZ_mm: 1.1mm; AEC Qualified: No; Gain Bandwidth: 1MHz; Input Bias Current: 10pA; Input Offset Voltage: 0.5mV; Max Dual Supply Voltage: 20V; Max Supply Voltage: 40V; Min Dual Supply Voltage: 2.25V; Min Supply Voltage: 4.5V; Nominal Supply Current: 150uA; Number Of Channels: 2; Output Current Per Channel: 60mA; Response Time: 6us; Standoff Height: 0mm; TaMax_C: +125°C; TaMin_C: -40°C; TJmax_C: +150°C; Voltage Gain: 130dB
U4 = CMP-0096504-1: 50-V, universal 4-20-mA, ±20-mA current loop protector 8-SOT-23-THIN -40 to 125; Manufacturer: Texas Instruments; TJmax_C: +125°C; Min Supply Voltage: 2.25V; AEC Qualified: No; Max Supply Voltage: 30V; SizeZ_mm: 1.1mm; Standoff Height: 0mm; Number Of Outputs: 1
U6 = CMP-0097359-1: 40-V, 1-MHz, RRO Operational Amplifiers for Cost-Sensitive Systems; Manufacturer: Texas Instruments; Input Bias Current: 0.00001uA; SizeZ_mm: 1.1mm; TJmax_C: +150°C; Min Supply Voltage: 4.5V; Min Dual Supply Voltage: 2.25V; Gain Bandwidth: 1MHz; Input Offset Voltage: 0.5mV; Number Of Channels: 1; Max Supply Voltage: 40V; Response Time: 6us; Standoff Height: 0mm; TaMin_C: -40°C; Max Dual Supply Voltage: 20V; TaMax_C: +125°C; Nominal Supply Current: 150uA; Output Current Per Channel: 60mA; Voltage Gain: 130dB; AEC Qualified: No
U7 = CMP-0092737-1: 40-V, dual-channel, 4.5-MHz, rail-to-rail input/output, low-offset-voltage, low-noise op amp 8-VSSOP -40 to 125; Manufacturer: Texas Instruments; Gain Bandwidth: 4.5MHz; SizeZ_mm: 1.1mm; Input Bias Current: 0.00001uA; Min Supply Voltage: 2.7V; Nominal Supply Current: 560uA; Max Supply Voltage: 40V; Number Of Channels: 2; Max Dual Supply Voltage: 20V; TJmax_C: +150°C; AEC Qualified: No; Output Current Per Channel: 75mA; Voltage Gain: 145dB; TaMax_C: +125°C; Min Dual Supply Voltage: 1.35V; TaMin_C: -40°C; Input Offset Voltage: 0.125mV; Standoff Height: 0.05mm; Response Time: 2.5us
U8 = CMP-0124197-1: Manufacturer: Texas Instruments; SizeZ_mm: 0.8mm; Standoff Height: 0mm
U9 U14 = CMP-0081715-3: 33 V Bidirectional Flat-Clamp Surge Protection Device, DRB0008A (VSON-8); Alternate PartNumber: TVS3301DRBT; Alternate Manufacturer: Texas Instruments; SizeZ_mm: 1.0; SizeX_mm: 3.0; AEC Category: Q200; SizeAreaWB_mm2: 16.0; CompType: IC; Rating: Catalog; SizeArea_mm2: 9.0; AEC Qualified: N
U10 = CMP-0123563-1: 1.65-V to 5.5-V 8-bit parallel-load shift register with voltage translation; Manufacturer: Texas Instruments; SizeZ_mm: 0.8mm; AEC Qualified: No; Frequency_Fixed: 37.7MHz; Max Supply Voltage: 5.5V; Min Supply Voltage: 1.65V; Nominal Supply Current: 2uA; Number Of Inputs: 8; Number Of Outputs: 2; PositionCount: 1; Standoff Height: 0mm; TaMax_C: +125°C; TaMin_C: -40°C
U11 = CMP-0051690-3: Single Inverter, DRL0005A, LARGE T&R; Manufacturer: Texas Instruments; Input Type: CMOS/TTL; 3-State Output: No; Voltage(Nom)(V): 1.8,2.5,3.3,5; Logic: Inverting; Technology Family: LVC; ICC @ Nom Voltage(Max)(mA): 0.01; Bits(#): 1; VCC(Max)(V): 5.5; Output Type: CMOS; Sub-Family: Inverting Buffer/Driver; tpd @ Nom Voltage(Max)(ns): 7.5,5.2,4.2,3.7; VCC(Min)(V): 1.65; Rating: Catalog; F @ Nom Voltage(Max)(Mhz): 150; Output Drive (IOL/IOH)(Max)(mA): 32/-32; AEC Category: Q200; AEC Qualified: N; CompType: IC; SizeX_mm: 1.6; SizeZ_mm: 0.6
U12 = CMP-0066783-1: 150-mA, 30-V, Ultra-Low IQ, Wide Input Low-Dropout Regulator with Reverse Current Protection, DBV0005A (SOT-23-5); Alternate PartNumber: TPS70950DBVT; Alternate Manufacturer: Texas Instruments; Green_Lifecycle: Active; SizeAreaWB_mm2: 14.82; Green_REACh: Passed; U/M: EA; SizeZ_mm: 1.45; SizeX_mm: 2.8; SizeY_mm: 2.9; SizeArea_mm2: 8.12; CompType: IC

## Sheet Hardware.SchDoc
size 431 x 279 mm; Date: Not shown in title block; ApprovedBy: Not shown in title block; CheckedBy: Not shown in title block; Author: Not shown in title block; CompanyName: Not shown in title block; Engineer: Not shown in title block; Organization: Not shown in title block; Address1: Not shown in title block; Address2: Not shown in title block; Address3: Not shown in title block; Address4: Not shown in title block; DocumentNumber: 3; Revision: Use project parameter SCH_Rev; SheetNumber: 3; SheetTotal: 3; PageSetup: Record=PageOptions¦CenterHorizontal=True¦CenterVertical=True¦PrintScale=1.00¦XCorrection=1.00¦YCorrection=1.00¦PrintKind=0¦BorderSize=5000000¦LeftOffset=0¦BottomOffset=0¦Orientation=2¦PaperLength=1000¦PaperWidth=1000¦Scale=100¦PaperSource=15¦PrintQuality=600¦MediaType=1¦DitherType=10¦PaperKind=Letter¦PrintScaleMode=1
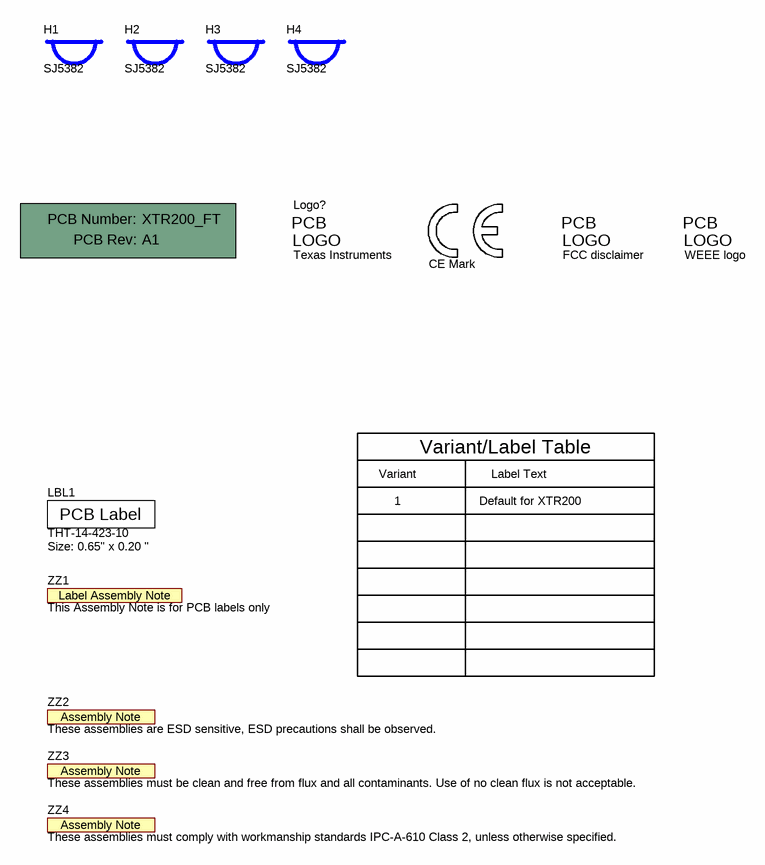
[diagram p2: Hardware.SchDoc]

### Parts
!PCB1  Printed Circuit Board  (value not drawn)  (mechanical)
H1  SJ5382  [3M_SJ5382]
H2  SJ5382  [3M_SJ5382]
H3  SJ5382  [3M_SJ5382]
H4  SJ5382  [3M_SJ5382]
LBL1  THT-14-423-10  Note: Size: 0.65" x 0.20 "  [Label_650x200]
Logo1  CE Mark  [CE_Mark_5mm]  (no BOM)
Logo3  FCC disclaimer  [FCC_disclaimer]  (no BOM)
Logo4  WEEE logo  [WEEE_Minimum]  (no BOM)
Logo?  Texas Instruments  [TI_Horizontal_Overlay_Medium]  (no BOM)
ZZ1  This Assembly Note is for PCB labels only  [AssemblyNoteLabel]  (no BOM)
ZZ2  These assemblies are ESD sensitive, ESD precautions shall be observed.  [AssemblyNote]  (no BOM)
ZZ3  These assemblies must be clean and free from flux and all contaminants. Use of no clean flux is not acceptable.  [AssemblyNote]  (no BOM)
ZZ4  These assemblies must comply with workmanship standards IPC-A-610 Class 2, unless otherwise specified.  [AssemblyNote]  (no BOM)

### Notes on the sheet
- Variant
- Variant/Label Table
- Label Text
- 1
- Default for XTR200

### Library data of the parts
!PCB1 = CMP-0003618-2: Manufacturer: Any; PartNumber: XTR200_FT
H1-H4 = CMP-0003668-1: Bumpon, Hemisphere, 0.25 X 0.075, Clear; Manufacturer: 3M
LBL1 = CMP-0003625-1: Thermal Transfer Printable Labels, 0.650" W x 0.200" H - 10,000 per roll; Manufacturer: Brady; CompType: Label
Logo1 = CMP-0074844-1: SymbolCreator: a0412235
Logo3 = CMP-0074847-1: FCC_disclaimer; Library Reference: Logo
Logo4 = CMP-0074769-1
Logo? = CMP-0074838-1: Texas Instrument Corporate Signature; SymbolCreator: a0412235; Lib Reference: TI_Logo
ZZ1 = CMP-0003616-3
ZZ2 = CMP-0077236-1
ZZ3 = CMP-0077237-1
ZZ4 = CMP-0077238-1

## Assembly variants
Variant 1 XTR200-FE: not fitted Q3 Q4 R26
